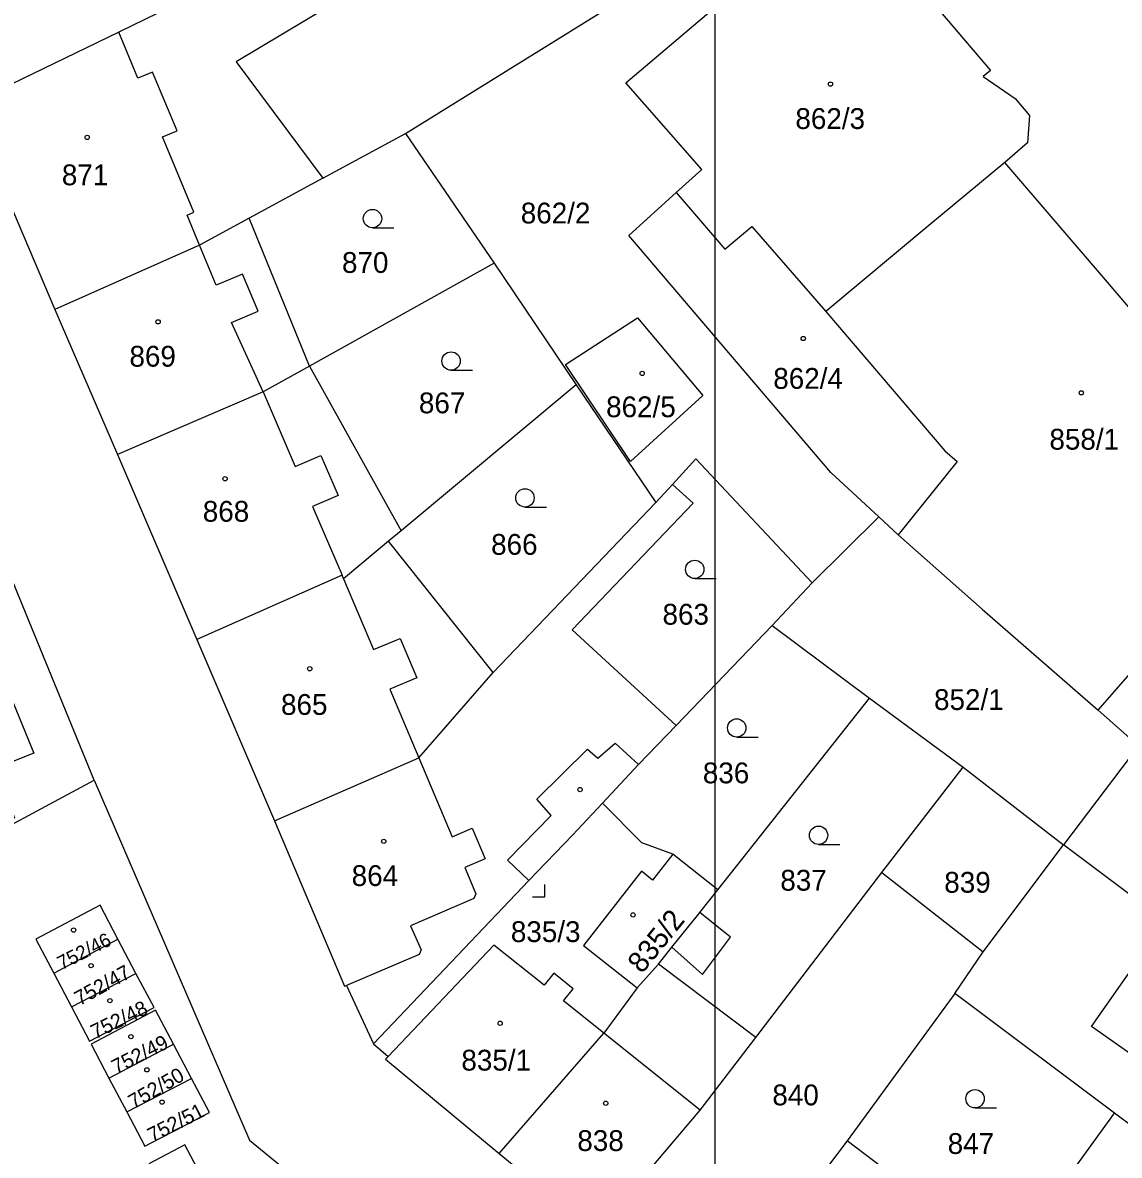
# Model space of a CAD drawing. Extents: x -496682 to -495776, y -1088797 to -1088018.
# Drawn here: x -496193.9 to -496104.3, y -1088306.6 to -1088214 of the extents above; entities that cross this region are included whole.
import ezdxf

# ---------------------------------------------------------------- set-up
doc = ezdxf.new("R2010")
doc.units = 0
for name, color, linetype in [('Hranice parcel', 7, 'Continuous'), ('Parcelní čísla', 7, 'Continuous'), ('Vnitřní kresba', 7, 'Continuous'), ('Vrstva 63', 7, 'Continuous'), ('Značky budov', 7, 'Continuous'), ('Značky kultur', 7, 'Continuous')]:
    doc.layers.add(name, color=color, linetype=linetype)

msp = doc.modelspace()

# ---------------------------------------------------------------- linework, layer by layer
at = {"layer": 'Hranice parcel'}
for p, q in [((-496162.6, -1088223.08), (-496138.52, -1088208.12)), ((-496198.35, -1088220.77), (-496191.24, -1088237.47)), ((-496169.35, -1088226.74), (-496162.6, -1088223.08)), ((-496162.6, -1088223.08), (-496155.35, -1088233.68)), ((-496169.35, -1088226.74), (-496175.38, -1088230.01)), ((-496170.44, -1088242.08), (-496175.38, -1088230.01)), ((-496155.35, -1088233.68), (-496170.44, -1088242.08)), ((-496155.35, -1088233.68), (-496148.66, -1088243.61)), ((-496191.24, -1088237.47), (-496186.12, -1088249.31)), ((-496170.44, -1088242.08), (-496162.94, -1088255.53)), ((-496148.66, -1088243.61), (-496162.94, -1088255.53)), ((-496148.66, -1088243.61), (-496142.14, -1088253.24)), ((-496188.02, -1088275.91), (-496199.66, -1088247.57)), ((-496186.12, -1088249.31), (-496179.65, -1088264.41)), ((-496142.14, -1088253.24), (-496140.78, -1088251.76)), ((-496155.43, -1088267.13), (-496142.14, -1088253.24)), ((-496129.39, -1088259.8), (-496123.95, -1088254.4)), ((-496122.37, -1088255.87), (-496123.95, -1088254.4)), ((-496162.94, -1088255.53), (-496163.98, -1088256.4)), ((-496155.43, -1088267.13), (-496163.98, -1088256.4)), ((-496132.65, -1088263.27), (-496129.39, -1088259.8)), ((-496140.49, -1088271.46), (-496132.65, -1088263.27)), ((-496132.65, -1088263.27), (-496124.69, -1088269.21)), ((-496179.65, -1088264.41), (-496173.29, -1088279.24)), ((-496137.09, -1088284.86), (-496124.69, -1088269.21)), ((-496124.69, -1088269.21), (-496117.05, -1088274.85)), ((-496102.73, -1088273.12), (-496106.03, -1088270.19)), ((-496102.73, -1088273.12), (-496108.86, -1088281.21)), ((-496123.68, -1088283.47), (-496117.05, -1088274.85)), ((-496117.05, -1088274.85), (-496108.86, -1088281.21)), ((-496219.91, -1088293.08), (-496188.02, -1088275.91)), ((-496115.43, -1088289.93), (-496108.86, -1088281.21)), ((-496100.55, -1088287.45), (-496108.86, -1088281.21)), ((-496137.09, -1088284.86), (-496140.75, -1088281.96)), ((-496133.98, -1088296.93), (-496123.68, -1088283.47)), ((-496123.68, -1088283.47), (-496115.43, -1088289.93)), ((-496152.52, -1088284.11), (-496165.22, -1088297.46)), ((-496191.33, -1088291.68), (-496186.08, -1088288.9)), ((-496184.61, -1088291.7), (-496186.08, -1088288.9)), ((-496117.73, -1088293.34), (-496115.43, -1088289.93)), ((-496191.33, -1088291.68), (-496189.88, -1088294.44)), ((-496189.88, -1088294.44), (-496184.61, -1088291.7)), ((-496143.68, -1088292.88), (-496141.93, -1088290.94)), ((-496133.98, -1088296.93), (-496141.93, -1088290.94)), ((-496143.68, -1088292.88), (-496146.4, -1088296.58)), ((-496117.73, -1088293.34), (-496126.53, -1088305.37)), ((-496104.68, -1088303.11), (-496117.73, -1088293.34)), ((-496154.95, -1088306.41), (-496146.4, -1088296.58)), ((-496186.82, -1088300.25), (-496181.56, -1088297.49)), ((-496180.08, -1088300.29), (-496181.56, -1088297.49)), ((-496165.22, -1088297.46), (-496164.02, -1088298.48)), ((-496186.82, -1088300.25), (-496185.36, -1088303.02)), ((-496185.36, -1088303.02), (-496180.08, -1088300.29)), ((-496113.5, -1088315.25), (-496104.68, -1088303.11)), ((-496118.15, -1088311.73), (-496126.53, -1088305.37)), ((-496154.95, -1088306.41), (-496147.01, -1088312.86))]:
    msp.add_line(p, q, dxfattribs=at)
for points in [[(-496135.52, -1088211.22), (-496134.74, -1088210.55), (-496130.01, -1088206.47), (-496126.43, -1088210.59), (-496123.42, -1088207.95), (-496118.45, -1088213.69), (-496114.82, -1088217.94), (-496115.42, -1088218.43), (-496112.79, -1088220.23), (-496111.62, -1088221.6), (-496111.79, -1088223.84), (-496113.66, -1088225.45)], [(-496179.86, -1088211.45), (-496179.28, -1088212.43), (-496171.58, -1088207.84), (-496168.73, -1088212.63), (-496176.42, -1088217.23), (-496169.35, -1088226.74)], [(-496140.48, -1088227.9), (-496138.4, -1088226.02), (-496144.6, -1088218.93), (-496135.52, -1088211.22)], [(-496179.86, -1088211.45), (-496182.82, -1088213.25), (-496186.02, -1088214.8), (-496198.35, -1088220.77)], [(-496071.36, -1088215.79), (-496073.4, -1088215.67), (-496077.32, -1088216.49), (-496080.87, -1088218.31), (-496083.31, -1088220.16), (-496097.53, -1088232.76), (-496098.07, -1088233.76), (-496098.04, -1088234.96), (-496102.26, -1088238.74), (-496105.26, -1088235.24), (-496113.66, -1088225.45)], [(-496113.66, -1088225.45), (-496118.91, -1088229.82), (-496119.69, -1088230.47), (-496128.26, -1088237.61)], [(-496123.95, -1088254.4), (-496127.85, -1088250.78), (-496144.37, -1088231.41), (-496140.48, -1088227.9)], [(-496140.48, -1088227.9), (-496136.51, -1088232.52), (-496134.32, -1088230.68), (-496128.26, -1088237.61)], [(-496175.38, -1088230.01), (-496179.42, -1088232.2), (-496191.24, -1088237.47)], [(-496128.26, -1088237.61), (-496118.54, -1088249.02), (-496117.55, -1088249.89), (-496122.37, -1088255.87)], [(-496144.21, -1088249.89), (-496149.54, -1088241.95), (-496143.66, -1088238.15), (-496138.31, -1088244.49), (-496144.21, -1088249.89)], [(-496170.44, -1088242.08), (-496174.22, -1088244.19), (-496186.12, -1088249.31)], [(-496140.78, -1088251.76), (-496138.88, -1088249.67), (-496129.39, -1088259.8)], [(-496140.78, -1088251.76), (-496139.1, -1088253.29), (-496148.98, -1088263.63), (-496140.49, -1088271.46)], [(-496163.98, -1088256.4), (-496167.65, -1088259.46), (-496167.78, -1088259.16), (-496179.65, -1088264.41)], [(-496122.37, -1088255.87), (-496115.51, -1088261.93), (-496106.03, -1088270.19)], [(-496224.27, -1088284.4), (-496221.97, -1088283.2), (-496218.31, -1088281.3), (-496217.38, -1088283.04), (-496208.49, -1088278.31), (-496215.03, -1088262.55), (-496203.26, -1088257.73), (-496201.7, -1088261.7), (-496198.45, -1088260.34), (-496192.96, -1088273.71), (-496196.19, -1088275), (-496194.54, -1088278.98), (-496202.44, -1088282.27), (-496202.01, -1088283.23), (-496220.05, -1088292.84)], [(-496106.03, -1088270.19), (-496100.99, -1088264.42), (-496098.08, -1088266.98)], [(-496173.29, -1088279.24), (-496161.51, -1088274.08), (-496155.43, -1088267.13)], [(-496140.49, -1088271.46), (-496143.57, -1088274.63), (-496146.52, -1088277.8)], [(-496188.02, -1088275.91), (-496175.34, -1088305.32), (-496115.85, -1088354.08), (-496107.5, -1088361.45)], [(-496146.52, -1088277.8), (-496148.95, -1088280.41), (-496152.52, -1088284.11)], [(-496140.75, -1088281.96), (-496143.3, -1088281.03), (-496146.52, -1088277.8)], [(-496173.29, -1088279.24), (-496167.59, -1088292.75), (-496167.42, -1088292.68), (-496165.22, -1088297.46)], [(-496140.75, -1088281.96), (-496142.42, -1088284.07), (-496143.32, -1088283.36), (-496148.07, -1088289.43), (-496143.68, -1088292.88)], [(-496141.93, -1088290.94), (-496140.84, -1088289.57), (-496138.76, -1088286.97), (-496138.57, -1088286.73), (-496137.09, -1088284.86)], [(-496186.08, -1088288.9), (-496187.54, -1088286.12), (-496192.79, -1088288.91), (-496191.33, -1088291.68)], [(-496095.45, -1088292.15), (-496100.96, -1088300), (-496106.57, -1088296.04), (-496101.08, -1088288.2)], [(-496146.4, -1088296.58), (-496149.69, -1088293.94), (-496148.9, -1088292.95), (-496150.49, -1088291.68), (-496151.28, -1088292.67), (-496155.37, -1088289.39), (-496164.02, -1088298.48)], [(-496189.88, -1088294.44), (-496188.41, -1088297.23), (-496183.13, -1088294.49), (-496184.61, -1088291.7)], [(-496181.56, -1088297.49), (-496183.02, -1088294.71), (-496188.28, -1088297.47), (-496186.82, -1088300.25)], [(-496147.01, -1088312.86), (-496138.54, -1088302.87), (-496133.98, -1088296.93)], [(-496164.02, -1088298.48), (-496164.23, -1088298.7), (-496154.95, -1088306.41)], [(-496185.36, -1088303.02), (-496183.89, -1088305.81), (-496178.62, -1088303.07), (-496180.08, -1088300.29)], [(-496092.02, -1088312.57), (-496101.47, -1088305.51), (-496104.68, -1088303.11)], [(-496126.53, -1088305.37), (-496130.83, -1088311.08), (-496137.88, -1088320.43)], [(-496181.09, -1088311.98), (-496178.12, -1088310.44), (-496180.61, -1088305.71), (-496183.56, -1088307.26), (-496181.09, -1088311.98)]]:
    msp.add_lwpolyline(points, dxfattribs=at)
at = {"layer": 'Vnitřní kresba'}
for p, q in [((-496184.45, -1088218.56), (-496186.02, -1088214.8)), ((-496183.25, -1088218.06), (-496184.45, -1088218.56)), ((-496181.25, -1088222.85), (-496183.25, -1088218.06)), ((-496182.45, -1088223.36), (-496181.25, -1088222.85)), ((-496179.88, -1088229.52), (-496182.45, -1088223.36)), ((-496180.43, -1088229.75), (-496179.88, -1088229.52)), ((-496179.42, -1088232.2), (-496180.43, -1088229.75)), ((-496178.06, -1088235.46), (-496179.42, -1088232.2)), ((-496175.91, -1088234.57), (-496178.06, -1088235.46)), ((-496174.62, -1088237.6), (-496175.91, -1088234.57)), ((-496176.8, -1088238.51), (-496174.62, -1088237.6)), ((-496174.22, -1088244.19), (-496176.8, -1088238.51)), ((-496174.22, -1088244.19), (-496171.6, -1088250.28)), ((-496171.6, -1088250.28), (-496169.51, -1088249.38)), ((-496169.51, -1088249.38), (-496168.1, -1088252.65)), ((-496168.1, -1088252.65), (-496170.2, -1088253.55)), ((-496170.2, -1088253.55), (-496167.78, -1088259.16)), ((-496167.65, -1088259.46), (-496165.22, -1088265.25)), ((-496165.22, -1088265.25), (-496163.03, -1088264.33)), ((-496163.03, -1088264.33), (-496161.68, -1088267.56)), ((-496161.68, -1088267.56), (-496163.87, -1088268.48)), ((-496163.87, -1088268.48), (-496161.51, -1088274.08)), ((-496146.88, -1088274.11), (-496145.47, -1088272.9)), ((-496145.47, -1088272.9), (-496143.57, -1088274.63)), ((-496161.51, -1088274.08), (-496158.8, -1088280.53)), ((-496151.86, -1088277.47), (-496147.73, -1088273.39)), ((-496147.73, -1088273.39), (-496146.88, -1088274.11)), ((-496150.7, -1088278.8), (-496151.86, -1088277.47)), ((-496154.26, -1088282.46), (-496150.7, -1088278.8)), ((-496158.8, -1088280.53), (-496157.14, -1088279.83)), ((-496157.14, -1088279.83), (-496156.09, -1088282.34)), ((-496156.09, -1088282.34), (-496157.75, -1088283.04)), ((-496152.52, -1088284.11), (-496154.26, -1088282.46)), ((-496157.75, -1088283.04), (-496156.84, -1088285.21)), ((-496156.84, -1088285.21), (-496157.03, -1088285.58)), ((-496157.03, -1088285.58), (-496162.2, -1088287.82)), ((-496136.04, -1088288.75), (-496138.57, -1088286.73)), ((-496162.2, -1088287.82), (-496161.32, -1088289.78)), ((-496138.33, -1088291.8), (-496136.04, -1088288.75)), ((-496161.32, -1088289.78), (-496161.48, -1088290.17)), ((-496140.84, -1088289.57), (-496138.33, -1088291.8)), ((-496161.48, -1088290.17), (-496167.42, -1088292.68)), ((-496138.54, -1088302.87), (-496146.4, -1088296.58))]:
    msp.add_line(p, q, dxfattribs=at)
at = {"layer": 'Vrstva 63'}
msp.add_lwpolyline([(-496137.346, -1088164.238), (-496137.346, -1088461.238), (-496557.346, -1088461.238), (-496557.346, -1088164.238)], close=True, dxfattribs=at)
at = {"layer": 'Značky budov'}
for centre in [(-496127.887, -1088219.049), (-496188.597, -1088223.399), (-496182.807, -1088238.469), (-496130.107, -1088239.829), (-496143.267, -1088242.679), (-496107.397, -1088244.269), (-496177.337, -1088251.289), (-496170.417, -1088266.809), (-496148.337, -1088276.679), (-496164.377, -1088280.909), (-496144.017, -1088286.919), (-496189.707, -1088288.159), (-496188.277, -1088291.069), (-496186.737, -1088293.929), (-496154.867, -1088295.769), (-496185.027, -1088296.869), (-496183.717, -1088299.579), (-496182.477, -1088302.219), (-496146.247, -1088302.309)]:
    msp.add_circle(centre, 0.175, dxfattribs=at)
at = {"layer": 'Značky kultur'}
for p, q in [((-496165.293, -1088230.78), (-496163.543, -1088230.78)), ((-496158.873, -1088242.42), (-496157.123, -1088242.42)), ((-496152.843, -1088253.6), (-496151.093, -1088253.6)), ((-496138.973, -1088259.44), (-496137.223, -1088259.44)), ((-496135.543, -1088272.4), (-496133.793, -1088272.4)), ((-496128.863, -1088281.17), (-496127.113, -1088281.17)), ((-496151.23, -1088285.45), (-496151.23, -1088284.45)), ((-496152.231, -1088285.45), (-496151.23, -1088285.45)), ((-496116.083, -1088302.69), (-496114.333, -1088302.69))]:
    msp.add_line(p, q, dxfattribs=at)
for centre in [(-496165.293, -1088230.03), (-496158.873, -1088241.67), (-496152.843, -1088252.85), (-496138.973, -1088258.69), (-496135.543, -1088271.65), (-496128.863, -1088280.42), (-496116.083, -1088301.94)]:
    msp.add_circle(centre, 0.75, dxfattribs=at)

# ---------------------------------------------------------------- texts
at = {"layer": 'Parcelní čísla'}
for s, p in [('862/3', (-496130.753, -1088222.71)), ('871', (-496190.664, -1088227.31)), ('862/2', (-496153.183, -1088230.43)), ('870', (-496167.784, -1088234.47)), ('869', (-496185.144, -1088242.13)), ('862/4', (-496132.56, -1088243.94)), ('867', (-496161.504, -1088245.94)), ('862/5', (-496146.213, -1088246.26)), ('858/1', (-496110.003, -1088248.91)), ('868', (-496179.154, -1088254.8)), ('866', (-496155.604, -1088257.5)), ('863', (-496141.604, -1088263.21)), ('852/1', (-496119.43, -1088270.18)), ('865', (-496172.764, -1088270.58)), ('836', (-496138.314, -1088276.17)), ('864', (-496166.994, -1088284.56)), ('837', (-496131.984, -1088284.94)), ('839', (-496118.594, -1088285.11)), ('835/3', (-496153.993, -1088289.14)), ('835/1', (-496158.033, -1088299.64)), ('840', (-496132.634, -1088302.48)), ('838', (-496148.564, -1088306.21)), ('847', (-496118.314, -1088306.45))]:
    msp.add_text(s, height=1.7, dxfattribs=at).set_placement(p)
for s, height, rotation, p in [('835/2', 1.7, 51, (-496143.284, -1088291.79)), ('752/46', 1.139, 27, (-496190.674, -1088291.452)), ('752/47', 1.2, 29, (-496189.219, -1088294.374)), ('752/48', 1.2, 26, (-496187.936, -1088297.099)), ('752/49', 1.2, 27, (-496186.217, -1088299.964)), ('752/50', 1.2, 30, (-496184.8, -1088302.819)), ('752/51', 1.2, 27, (-496183.277, -1088305.544))]:
    msp.add_text(s, height=height, rotation=rotation, dxfattribs=at).set_placement(p)

doc.saveas('drawing.dxf')
